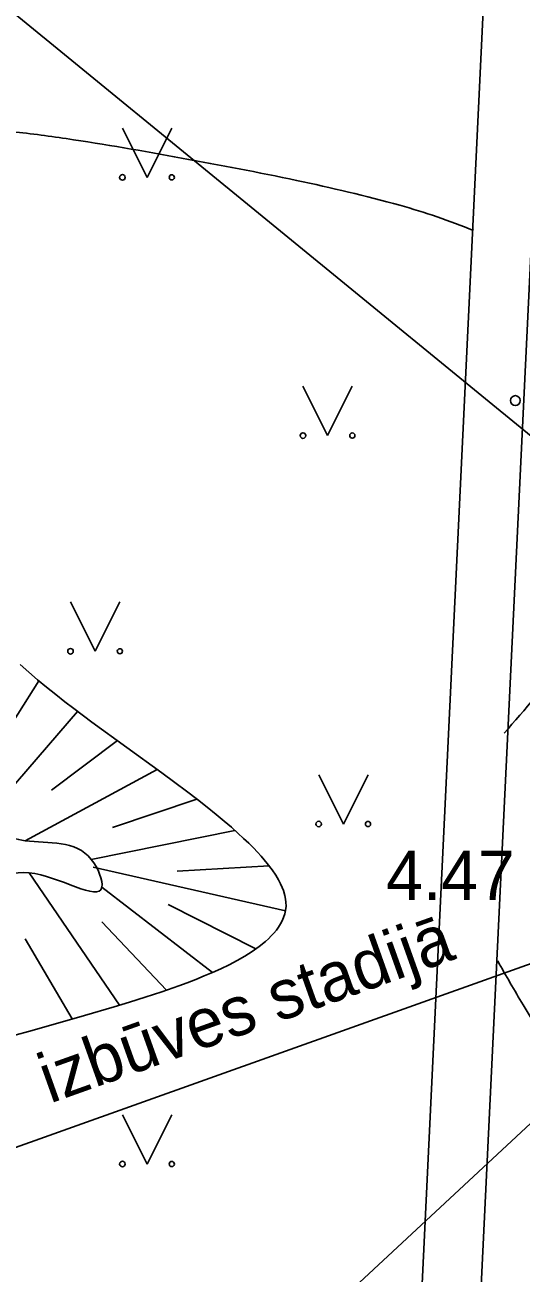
# Model space of a CAD drawing. Extents: x 519536 to 519949, y 326041 to 326519.
# Drawn here: x 519766.26 to 519771.29, y 326171.4 to 326184.04 of the extents above; entities that cross this region are included whole.
import ezdxf

# ---------------------------------------------------------------- set-up
doc = ezdxf.new("R2010")
doc.units = 0
for name, color, linetype in [('APGR_SARK_####_####_#', 7, 'Continuous'), ('CELI_CMAL_####_####_#', 7, 'Continuous'), ('ELEK_VADP_ZSPR_####_#', 7, 'Continuous'), ('ELEK_VADP_ZSPR_TKST_#', 7, 'Continuous'), ('RELJ_AATZ_####_TKST_#', 7, 'Continuous'), ('RELJ_ELEM_####_####_#', 7, 'Continuous'), ('RELJ_HORZ_PAMT_####_#', 7, 'Continuous'), ('RELJ_NOGA_####_####_#', 7, 'Continuous'), ('RELJ_NOGL_####_####_#', 7, 'Continuous'), ('TERT_ELEM_####_####_#', 7, 'Continuous')]:
    doc.layers.add(name, color=color, linetype=linetype)

msp = doc.modelspace()

# ---------------------------------------------------------------- linework, layer by layer
at = {"layer": 'APGR_SARK_####_####_#'}
msp.add_line((519795.048, 326160.518), (519743.353, 326202.822), dxfattribs=at)
at = {"layer": 'CELI_CMAL_####_####_#'}
for points in [[(519763.587, 326157.215), (519770.88, 326171.123), (519771.729, 326188.814)], [(519763.133, 326157.642), (519770.288, 326171.285), (519771.113, 326188.496)]]:
    msp.add_lwpolyline(points, dxfattribs=at)
at = {"layer": 'ELEK_VADP_ZSPR_####_#'}
for points in [[(519746.947, 326150.185), (519783.147, 326183.851)], [(519785.405, 326179.533), (519755.855, 326168.99), (519734.736, 326159.988)]]:
    msp.add_lwpolyline(points, dxfattribs=at)
at = {"layer": 'RELJ_ELEM_####_####_#'}
msp.add_circle((519771.232, 326180.238), 0.05, dxfattribs=at)
at = {"layer": 'RELJ_HORZ_PAMT_####_#'}
for points in [[(519770.809, 326181.961), (519770.439, 326182.101), (519770.061, 326182.217), (519769.015, 326182.469), (519767.848, 326182.696), (519766.681, 326182.893), (519766.096, 326182.968), (519765.511, 326183.019), (519764.34, 326183.029), (519763.423, 326182.977)], [(519771.119, 326176.866), (519771.758, 326177.593), (519772.434, 326178.342), (519772.717, 326178.722), (519772.84, 326178.926), (519772.953, 326179.138), (519773.08, 326179.49), (519773.142, 326179.887), (519773.017, 326180.455), (519772.962, 326180.535), (519772.895, 326180.61)], [(519768.004, 326165.685), (519768.164, 326165.52), (519768.521, 326165.128), (519768.866, 326164.727), (519769.209, 326164.324), (519769.561, 326163.927), (519769.853, 326163.625), (519770.159, 326163.339), (519770.477, 326163.065), (519770.81, 326162.801), (519770.935, 326162.731), (519771.076, 326162.693), (519771.22, 326162.688), (519771.355, 326162.718), (519771.497, 326162.794), (519771.626, 326162.886), (519771.832, 326163.118), (519771.927, 326163.282), (519772.011, 326163.445), (519772.147, 326163.775), (519772.241, 326164.11), (519772.291, 326164.456), (519772.388, 326165.88), (519772.458, 326167.182), (519772.505, 326168.485), (519772.477, 326170.437), (519772.43, 326171.086), (519772.384, 326171.43), (519772.315, 326171.771), (519772.138, 326172.444), (519771.785, 326173.298), (519771.311, 326174.112), (519771.053, 326174.558)]]:
    msp.add_spline(points, degree=3, dxfattribs=at)
at = {"layer": 'RELJ_NOGA_####_####_#'}
for p, q in [((519766.403, 326177.397), (519765.862, 326176.544)), ((519766.795, 326177.088), (519765.768, 326175.898)), ((519767.199, 326176.792), (519766.533, 326176.288)), ((519767.603, 326176.498), (519766.265, 326175.777)), ((519768.004, 326176.199), (519767.149, 326175.911)), ((519768.39, 326175.882), (519766.935, 326175.588)), ((519768.902, 326175.066), (519766.952, 326175.509)), ((519768.737, 326175.522), (519767.806, 326175.467)), ((519767.221, 326174.11), (519766.305, 326175.453)), ((519768.164, 326174.442), (519767.042, 326175.305)), ((519768.602, 326174.681), (519767.713, 326175.13)), ((519767.697, 326174.263), (519767.042, 326174.955)), ((519766.741, 326173.97), (519766.265, 326174.781))]:
    msp.add_line(p, q, dxfattribs=at)
msp.add_lwpolyline([(519766.215, 326177.562), (519766.302, 326177.484), (519766.391, 326177.407), (519766.482, 326177.332), (519766.574, 326177.258), (519766.665, 326177.186), (519766.757, 326177.117), (519766.939, 326176.98), (519767.65, 326176.464), (519767.781, 326176.368), (519767.901, 326176.278), (519768.01, 326176.194), (519768.11, 326176.116), (519768.2, 326176.044), (519768.281, 326175.976), (519768.354, 326175.914), (519768.42, 326175.855), (519768.478, 326175.801), (519768.531, 326175.751), (519768.577, 326175.704), (519768.619, 326175.661), (519768.655, 326175.621), (519768.718, 326175.547), (519768.767, 326175.483), (519768.804, 326175.428), (519768.832, 326175.38), (519768.853, 326175.339), (519768.869, 326175.304), (519768.881, 326175.274), (519768.897, 326175.221), (519768.904, 326175.183), (519768.907, 326175.154), (519768.908, 326175.112), (519768.903, 326175.071), (519768.895, 326175.035), (519768.883, 326175), (519768.869, 326174.966), (519768.852, 326174.933), (519768.832, 326174.901), (519768.81, 326174.871), (519768.785, 326174.841), (519768.759, 326174.812), (519768.73, 326174.784), (519768.7, 326174.756), (519768.635, 326174.704), (519768.565, 326174.654), (519768.49, 326174.607), (519768.412, 326174.562), (519768.331, 326174.52), (519768.248, 326174.48), (519768.164, 326174.442), (519768.078, 326174.406), (519767.993, 326174.371), (519767.907, 326174.338), (519767.822, 326174.306), (519767.65, 326174.246), (519767.482, 326174.191), (519767.321, 326174.14), (519767.165, 326174.093), (519766.867, 326174.006), (519766.335, 326173.855), (519766.136, 326173.798)], dxfattribs=at)
msp.add_lwpolyline([(519766.215, 326177.562), (519766.302, 326177.484), (519766.391, 326177.407), (519766.482, 326177.332), (519766.574, 326177.258), (519766.665, 326177.186), (519766.757, 326177.117), (519766.939, 326176.98), (519767.65, 326176.464), (519767.781, 326176.368), (519767.901, 326176.278), (519768.01, 326176.194), (519768.11, 326176.116), (519768.2, 326176.044), (519768.281, 326175.976), (519768.354, 326175.914), (519768.42, 326175.855), (519768.478, 326175.801), (519768.531, 326175.751), (519768.577, 326175.704), (519768.619, 326175.661), (519768.655, 326175.621), (519768.718, 326175.547), (519768.767, 326175.483), (519768.804, 326175.428), (519768.832, 326175.38), (519768.853, 326175.339), (519768.869, 326175.304), (519768.881, 326175.274), (519768.897, 326175.221), (519768.904, 326175.183), (519768.907, 326175.154), (519768.908, 326175.112), (519768.903, 326175.071), (519768.895, 326175.035), (519768.883, 326175), (519768.869, 326174.966), (519768.852, 326174.933), (519768.832, 326174.901), (519768.81, 326174.871), (519768.785, 326174.841), (519768.759, 326174.812), (519768.73, 326174.784), (519768.7, 326174.756), (519768.635, 326174.704), (519768.565, 326174.654), (519768.49, 326174.607), (519768.412, 326174.562), (519768.331, 326174.52), (519768.248, 326174.48), (519768.164, 326174.442), (519768.078, 326174.406), (519767.993, 326174.371), (519767.907, 326174.338), (519767.822, 326174.306), (519767.65, 326174.246), (519767.482, 326174.191), (519767.321, 326174.14), (519767.165, 326174.093), (519766.867, 326174.006), (519766.335, 326173.855), (519766.136, 326173.798)], dxfattribs=at)
msp.add_lwpolyline([(519766.215, 326177.562), (519766.302, 326177.484), (519766.391, 326177.407), (519766.482, 326177.332), (519766.574, 326177.258), (519766.665, 326177.186), (519766.757, 326177.117), (519766.939, 326176.98), (519767.65, 326176.464), (519767.781, 326176.368), (519767.901, 326176.278), (519768.01, 326176.194), (519768.11, 326176.116), (519768.2, 326176.044), (519768.281, 326175.976), (519768.354, 326175.914), (519768.42, 326175.855), (519768.478, 326175.801), (519768.531, 326175.751), (519768.577, 326175.704), (519768.619, 326175.661), (519768.655, 326175.621), (519768.718, 326175.547), (519768.767, 326175.483), (519768.804, 326175.428), (519768.832, 326175.38), (519768.853, 326175.339), (519768.869, 326175.304), (519768.881, 326175.274), (519768.897, 326175.221), (519768.904, 326175.183), (519768.907, 326175.154), (519768.908, 326175.112), (519768.903, 326175.071), (519768.895, 326175.035), (519768.883, 326175), (519768.869, 326174.966), (519768.852, 326174.933), (519768.832, 326174.901), (519768.81, 326174.871), (519768.785, 326174.841), (519768.759, 326174.812), (519768.73, 326174.784), (519768.7, 326174.756), (519768.635, 326174.704), (519768.565, 326174.654), (519768.49, 326174.607), (519768.412, 326174.562), (519768.331, 326174.52), (519768.248, 326174.48), (519768.164, 326174.442), (519768.078, 326174.406), (519767.993, 326174.371), (519767.907, 326174.338), (519767.822, 326174.306), (519767.65, 326174.246), (519767.482, 326174.191), (519767.321, 326174.14), (519767.165, 326174.093), (519766.867, 326174.006), (519766.335, 326173.855), (519766.136, 326173.798)], dxfattribs=at)
msp.add_lwpolyline([(519766.215, 326177.562), (519766.302, 326177.484), (519766.391, 326177.407), (519766.482, 326177.332), (519766.574, 326177.258), (519766.665, 326177.186), (519766.757, 326177.117), (519766.939, 326176.98), (519767.65, 326176.464), (519767.781, 326176.368), (519767.901, 326176.278), (519768.01, 326176.194), (519768.11, 326176.116), (519768.2, 326176.044), (519768.281, 326175.976), (519768.354, 326175.914), (519768.42, 326175.855), (519768.478, 326175.801), (519768.531, 326175.751), (519768.577, 326175.704), (519768.619, 326175.661), (519768.655, 326175.621), (519768.718, 326175.547), (519768.767, 326175.483), (519768.804, 326175.428), (519768.832, 326175.38), (519768.853, 326175.339), (519768.869, 326175.304), (519768.881, 326175.274), (519768.897, 326175.221), (519768.904, 326175.183), (519768.907, 326175.154), (519768.908, 326175.112), (519768.903, 326175.071), (519768.895, 326175.035), (519768.883, 326175), (519768.869, 326174.966), (519768.852, 326174.933), (519768.832, 326174.901), (519768.81, 326174.871), (519768.785, 326174.841), (519768.759, 326174.812), (519768.73, 326174.784), (519768.7, 326174.756), (519768.635, 326174.704), (519768.565, 326174.654), (519768.49, 326174.607), (519768.412, 326174.562), (519768.331, 326174.52), (519768.248, 326174.48), (519768.164, 326174.442), (519768.078, 326174.406), (519767.993, 326174.371), (519767.907, 326174.338), (519767.822, 326174.306), (519767.65, 326174.246), (519767.482, 326174.191), (519767.321, 326174.14), (519767.165, 326174.093), (519766.867, 326174.006), (519766.335, 326173.855), (519766.136, 326173.798)], dxfattribs=at)
msp.add_lwpolyline([(519766.215, 326177.562), (519766.302, 326177.484), (519766.391, 326177.407), (519766.482, 326177.332), (519766.574, 326177.258), (519766.665, 326177.186), (519766.757, 326177.117), (519766.939, 326176.98), (519767.65, 326176.464), (519767.781, 326176.368), (519767.901, 326176.278), (519768.01, 326176.194), (519768.11, 326176.116), (519768.2, 326176.044), (519768.281, 326175.976), (519768.354, 326175.914), (519768.42, 326175.855), (519768.478, 326175.801), (519768.531, 326175.751), (519768.577, 326175.704), (519768.619, 326175.661), (519768.655, 326175.621), (519768.718, 326175.547), (519768.767, 326175.483), (519768.804, 326175.428), (519768.832, 326175.38), (519768.853, 326175.339), (519768.869, 326175.304), (519768.881, 326175.274), (519768.897, 326175.221), (519768.904, 326175.183), (519768.907, 326175.154), (519768.908, 326175.112), (519768.903, 326175.071), (519768.895, 326175.035), (519768.883, 326175), (519768.869, 326174.966), (519768.852, 326174.933), (519768.832, 326174.901), (519768.81, 326174.871), (519768.785, 326174.841), (519768.759, 326174.812), (519768.73, 326174.784), (519768.7, 326174.756), (519768.635, 326174.704), (519768.565, 326174.654), (519768.49, 326174.607), (519768.412, 326174.562), (519768.331, 326174.52), (519768.248, 326174.48), (519768.164, 326174.442), (519768.078, 326174.406), (519767.993, 326174.371), (519767.907, 326174.338), (519767.822, 326174.306), (519767.65, 326174.246), (519767.482, 326174.191), (519767.321, 326174.14), (519767.165, 326174.093), (519766.867, 326174.006), (519766.335, 326173.855), (519766.136, 326173.798)], dxfattribs=at)
msp.add_lwpolyline([(519766.215, 326177.562), (519766.302, 326177.484), (519766.391, 326177.407), (519766.482, 326177.332), (519766.574, 326177.258), (519766.665, 326177.186), (519766.757, 326177.117), (519766.939, 326176.98), (519767.65, 326176.464), (519767.781, 326176.368), (519767.901, 326176.278), (519768.01, 326176.194), (519768.11, 326176.116), (519768.2, 326176.044), (519768.281, 326175.976), (519768.354, 326175.914), (519768.42, 326175.855), (519768.478, 326175.801), (519768.531, 326175.751), (519768.577, 326175.704), (519768.619, 326175.661), (519768.655, 326175.621), (519768.718, 326175.547), (519768.767, 326175.483), (519768.804, 326175.428), (519768.832, 326175.38), (519768.853, 326175.339), (519768.869, 326175.304), (519768.881, 326175.274), (519768.897, 326175.221), (519768.904, 326175.183), (519768.907, 326175.154), (519768.908, 326175.112), (519768.903, 326175.071), (519768.895, 326175.035), (519768.883, 326175), (519768.869, 326174.966), (519768.852, 326174.933), (519768.832, 326174.901), (519768.81, 326174.871), (519768.785, 326174.841), (519768.759, 326174.812), (519768.73, 326174.784), (519768.7, 326174.756), (519768.635, 326174.704), (519768.565, 326174.654), (519768.49, 326174.607), (519768.412, 326174.562), (519768.331, 326174.52), (519768.248, 326174.48), (519768.164, 326174.442), (519768.078, 326174.406), (519767.993, 326174.371), (519767.907, 326174.338), (519767.822, 326174.306), (519767.65, 326174.246), (519767.482, 326174.191), (519767.321, 326174.14), (519767.165, 326174.093), (519766.867, 326174.006), (519766.335, 326173.855), (519766.136, 326173.798)], dxfattribs=at)
msp.add_lwpolyline([(519766.215, 326177.562), (519766.302, 326177.484), (519766.391, 326177.407), (519766.482, 326177.332), (519766.574, 326177.258), (519766.665, 326177.186), (519766.757, 326177.117), (519766.939, 326176.98), (519767.65, 326176.464), (519767.781, 326176.368), (519767.901, 326176.278), (519768.01, 326176.194), (519768.11, 326176.116), (519768.2, 326176.044), (519768.281, 326175.976), (519768.354, 326175.914), (519768.42, 326175.855), (519768.478, 326175.801), (519768.531, 326175.751), (519768.577, 326175.704), (519768.619, 326175.661), (519768.655, 326175.621), (519768.718, 326175.547), (519768.767, 326175.483), (519768.804, 326175.428), (519768.832, 326175.38), (519768.853, 326175.339), (519768.869, 326175.304), (519768.881, 326175.274), (519768.897, 326175.221), (519768.904, 326175.183), (519768.907, 326175.154), (519768.908, 326175.112), (519768.903, 326175.071), (519768.895, 326175.035), (519768.883, 326175), (519768.869, 326174.966), (519768.852, 326174.933), (519768.832, 326174.901), (519768.81, 326174.871), (519768.785, 326174.841), (519768.759, 326174.812), (519768.73, 326174.784), (519768.7, 326174.756), (519768.635, 326174.704), (519768.565, 326174.654), (519768.49, 326174.607), (519768.412, 326174.562), (519768.331, 326174.52), (519768.248, 326174.48), (519768.164, 326174.442), (519768.078, 326174.406), (519767.993, 326174.371), (519767.907, 326174.338), (519767.822, 326174.306), (519767.65, 326174.246), (519767.482, 326174.191), (519767.321, 326174.14), (519767.165, 326174.093), (519766.867, 326174.006), (519766.335, 326173.855), (519766.136, 326173.798)], dxfattribs=at)
msp.add_lwpolyline([(519766.215, 326177.562), (519766.302, 326177.484), (519766.391, 326177.407), (519766.482, 326177.332), (519766.574, 326177.258), (519766.665, 326177.186), (519766.757, 326177.117), (519766.939, 326176.98), (519767.65, 326176.464), (519767.781, 326176.368), (519767.901, 326176.278), (519768.01, 326176.194), (519768.11, 326176.116), (519768.2, 326176.044), (519768.281, 326175.976), (519768.354, 326175.914), (519768.42, 326175.855), (519768.478, 326175.801), (519768.531, 326175.751), (519768.577, 326175.704), (519768.619, 326175.661), (519768.655, 326175.621), (519768.718, 326175.547), (519768.767, 326175.483), (519768.804, 326175.428), (519768.832, 326175.38), (519768.853, 326175.339), (519768.869, 326175.304), (519768.881, 326175.274), (519768.897, 326175.221), (519768.904, 326175.183), (519768.907, 326175.154), (519768.908, 326175.112), (519768.903, 326175.071), (519768.895, 326175.035), (519768.883, 326175), (519768.869, 326174.966), (519768.852, 326174.933), (519768.832, 326174.901), (519768.81, 326174.871), (519768.785, 326174.841), (519768.759, 326174.812), (519768.73, 326174.784), (519768.7, 326174.756), (519768.635, 326174.704), (519768.565, 326174.654), (519768.49, 326174.607), (519768.412, 326174.562), (519768.331, 326174.52), (519768.248, 326174.48), (519768.164, 326174.442), (519768.078, 326174.406), (519767.993, 326174.371), (519767.907, 326174.338), (519767.822, 326174.306), (519767.65, 326174.246), (519767.482, 326174.191), (519767.321, 326174.14), (519767.165, 326174.093), (519766.867, 326174.006), (519766.335, 326173.855), (519766.136, 326173.798)], dxfattribs=at)
msp.add_lwpolyline([(519766.215, 326177.562), (519766.302, 326177.484), (519766.391, 326177.407), (519766.482, 326177.332), (519766.574, 326177.258), (519766.665, 326177.186), (519766.757, 326177.117), (519766.939, 326176.98), (519767.65, 326176.464), (519767.781, 326176.368), (519767.901, 326176.278), (519768.01, 326176.194), (519768.11, 326176.116), (519768.2, 326176.044), (519768.281, 326175.976), (519768.354, 326175.914), (519768.42, 326175.855), (519768.478, 326175.801), (519768.531, 326175.751), (519768.577, 326175.704), (519768.619, 326175.661), (519768.655, 326175.621), (519768.718, 326175.547), (519768.767, 326175.483), (519768.804, 326175.428), (519768.832, 326175.38), (519768.853, 326175.339), (519768.869, 326175.304), (519768.881, 326175.274), (519768.897, 326175.221), (519768.904, 326175.183), (519768.907, 326175.154), (519768.908, 326175.112), (519768.903, 326175.071), (519768.895, 326175.035), (519768.883, 326175), (519768.869, 326174.966), (519768.852, 326174.933), (519768.832, 326174.901), (519768.81, 326174.871), (519768.785, 326174.841), (519768.759, 326174.812), (519768.73, 326174.784), (519768.7, 326174.756), (519768.635, 326174.704), (519768.565, 326174.654), (519768.49, 326174.607), (519768.412, 326174.562), (519768.331, 326174.52), (519768.248, 326174.48), (519768.164, 326174.442), (519768.078, 326174.406), (519767.993, 326174.371), (519767.907, 326174.338), (519767.822, 326174.306), (519767.65, 326174.246), (519767.482, 326174.191), (519767.321, 326174.14), (519767.165, 326174.093), (519766.867, 326174.006), (519766.335, 326173.855), (519766.136, 326173.798)], dxfattribs=at)
msp.add_lwpolyline([(519766.215, 326177.562), (519766.302, 326177.484), (519766.391, 326177.407), (519766.482, 326177.332), (519766.574, 326177.258), (519766.665, 326177.186), (519766.757, 326177.117), (519766.939, 326176.98), (519767.65, 326176.464), (519767.781, 326176.368), (519767.901, 326176.278), (519768.01, 326176.194), (519768.11, 326176.116), (519768.2, 326176.044), (519768.281, 326175.976), (519768.354, 326175.914), (519768.42, 326175.855), (519768.478, 326175.801), (519768.531, 326175.751), (519768.577, 326175.704), (519768.619, 326175.661), (519768.655, 326175.621), (519768.718, 326175.547), (519768.767, 326175.483), (519768.804, 326175.428), (519768.832, 326175.38), (519768.853, 326175.339), (519768.869, 326175.304), (519768.881, 326175.274), (519768.897, 326175.221), (519768.904, 326175.183), (519768.907, 326175.154), (519768.908, 326175.112), (519768.903, 326175.071), (519768.895, 326175.035), (519768.883, 326175), (519768.869, 326174.966), (519768.852, 326174.933), (519768.832, 326174.901), (519768.81, 326174.871), (519768.785, 326174.841), (519768.759, 326174.812), (519768.73, 326174.784), (519768.7, 326174.756), (519768.635, 326174.704), (519768.565, 326174.654), (519768.49, 326174.607), (519768.412, 326174.562), (519768.331, 326174.52), (519768.248, 326174.48), (519768.164, 326174.442), (519768.078, 326174.406), (519767.993, 326174.371), (519767.907, 326174.338), (519767.822, 326174.306), (519767.65, 326174.246), (519767.482, 326174.191), (519767.321, 326174.14), (519767.165, 326174.093), (519766.867, 326174.006), (519766.335, 326173.855), (519766.136, 326173.798)], dxfattribs=at)
msp.add_lwpolyline([(519766.215, 326177.562), (519766.302, 326177.484), (519766.391, 326177.407), (519766.482, 326177.332), (519766.574, 326177.258), (519766.665, 326177.186), (519766.757, 326177.117), (519766.939, 326176.98), (519767.65, 326176.464), (519767.781, 326176.368), (519767.901, 326176.278), (519768.01, 326176.194), (519768.11, 326176.116), (519768.2, 326176.044), (519768.281, 326175.976), (519768.354, 326175.914), (519768.42, 326175.855), (519768.478, 326175.801), (519768.531, 326175.751), (519768.577, 326175.704), (519768.619, 326175.661), (519768.655, 326175.621), (519768.718, 326175.547), (519768.767, 326175.483), (519768.804, 326175.428), (519768.832, 326175.38), (519768.853, 326175.339), (519768.869, 326175.304), (519768.881, 326175.274), (519768.897, 326175.221), (519768.904, 326175.183), (519768.907, 326175.154), (519768.908, 326175.112), (519768.903, 326175.071), (519768.895, 326175.035), (519768.883, 326175), (519768.869, 326174.966), (519768.852, 326174.933), (519768.832, 326174.901), (519768.81, 326174.871), (519768.785, 326174.841), (519768.759, 326174.812), (519768.73, 326174.784), (519768.7, 326174.756), (519768.635, 326174.704), (519768.565, 326174.654), (519768.49, 326174.607), (519768.412, 326174.562), (519768.331, 326174.52), (519768.248, 326174.48), (519768.164, 326174.442), (519768.078, 326174.406), (519767.993, 326174.371), (519767.907, 326174.338), (519767.822, 326174.306), (519767.65, 326174.246), (519767.482, 326174.191), (519767.321, 326174.14), (519767.165, 326174.093), (519766.867, 326174.006), (519766.335, 326173.855), (519766.136, 326173.798)], dxfattribs=at)
msp.add_lwpolyline([(519766.215, 326177.562), (519766.302, 326177.484), (519766.391, 326177.407), (519766.482, 326177.332), (519766.574, 326177.258), (519766.665, 326177.186), (519766.757, 326177.117), (519766.939, 326176.98), (519767.65, 326176.464), (519767.781, 326176.368), (519767.901, 326176.278), (519768.01, 326176.194), (519768.11, 326176.116), (519768.2, 326176.044), (519768.281, 326175.976), (519768.354, 326175.914), (519768.42, 326175.855), (519768.478, 326175.801), (519768.531, 326175.751), (519768.577, 326175.704), (519768.619, 326175.661), (519768.655, 326175.621), (519768.718, 326175.547), (519768.767, 326175.483), (519768.804, 326175.428), (519768.832, 326175.38), (519768.853, 326175.339), (519768.869, 326175.304), (519768.881, 326175.274), (519768.897, 326175.221), (519768.904, 326175.183), (519768.907, 326175.154), (519768.908, 326175.112), (519768.903, 326175.071), (519768.895, 326175.035), (519768.883, 326175), (519768.869, 326174.966), (519768.852, 326174.933), (519768.832, 326174.901), (519768.81, 326174.871), (519768.785, 326174.841), (519768.759, 326174.812), (519768.73, 326174.784), (519768.7, 326174.756), (519768.635, 326174.704), (519768.565, 326174.654), (519768.49, 326174.607), (519768.412, 326174.562), (519768.331, 326174.52), (519768.248, 326174.48), (519768.164, 326174.442), (519768.078, 326174.406), (519767.993, 326174.371), (519767.907, 326174.338), (519767.822, 326174.306), (519767.65, 326174.246), (519767.482, 326174.191), (519767.321, 326174.14), (519767.165, 326174.093), (519766.867, 326174.006), (519766.335, 326173.855), (519766.136, 326173.798)], dxfattribs=at)
at = {"layer": 'RELJ_NOGL_####_####_#'}
msp.add_spline([(519750.737, 326177.254), (519750.215, 326177.377), (519749.969, 326177.484), (519750.048, 326177.953), (519750.261, 326178.326), (519750.676, 326178.661), (519751.369, 326179.175), (519752.072, 326179.621), (519752.69, 326179.926), (519753.234, 326180.089), (519753.479, 326180.102), (519753.717, 326179.972), (519754.546, 326179.412), (519755.374, 326178.852), (519756.203, 326178.292), (519757.672, 326177.735), (519758.639, 326177.481), (519759.607, 326177.228), (519760.574, 326176.974), (519761.541, 326176.72), (519762.508, 326176.467), (519763.476, 326176.213), (519764.443, 326175.959), (519765.393, 326175.925), (519765.768, 326175.898), (519766.265, 326175.777), (519766.935, 326175.588), (519767.042, 326175.305), (519766.305, 326175.453), (519765.567, 326175.211), (519764.648, 326175.432), (519763.823, 326175.243), (519762.834, 326175.091), (519761.846, 326174.939), (519761.533, 326174.895), (519760.55, 326175.08), (519759.567, 326175.264), (519758.585, 326175.449), (519757.602, 326175.634), (519756.619, 326175.819), (519755.636, 326176.003), (519754.653, 326176.188), (519753.671, 326176.373), (519752.688, 326176.558), (519752.282, 326176.749), (519751.361, 326177.138), (519750.737, 326177.254)], degree=3, dxfattribs=at)
at = {"layer": 'TERT_ELEM_####_####_#'}
for p, q in [((519767.25, 326183), (519767.5, 326182.5)), ((519767.5, 326182.5), (519767.75, 326183)), ((519769.08, 326180.383), (519769.33, 326179.883)), ((519769.33, 326179.883), (519769.58, 326180.383)), ((519766.724, 326178.198), (519766.974, 326177.698)), ((519766.974, 326177.698), (519767.224, 326178.198)), ((519769.239, 326176.446), (519769.489, 326175.946)), ((519769.489, 326175.946), (519769.739, 326176.446)), ((519767.25, 326173), (519767.5, 326172.5)), ((519767.5, 326172.5), (519767.75, 326173))]:
    msp.add_line(p, q, dxfattribs=at)
for centre, radius in [((519767.25, 326182.5), 0.028), ((519767.75, 326182.5), 0.0263), ((519769.08, 326179.883), 0.028), ((519769.58, 326179.883), 0.0263), ((519766.724, 326177.697), 0.028), ((519767.224, 326177.697), 0.0263), ((519769.239, 326175.946), 0.028), ((519769.739, 326175.946), 0.0263), ((519767.25, 326172.5), 0.028), ((519767.75, 326172.5), 0.0263)]:
    msp.add_circle(centre, radius, dxfattribs=at)

# ---------------------------------------------------------------- texts
at = {"layer": 'ELEK_VADP_ZSPR_TKST_#'}
msp.add_text('izbūves stadijā', height=0.5, rotation=19.6351, dxfattribs=at).set_placement((519766.514, 326173.111))
at = {"layer": 'RELJ_AATZ_####_TKST_#'}
msp.add_text('4.47', height=0.5, dxfattribs=at).set_placement((519769.923, 326175.176))

doc.saveas('drawing.dxf')
